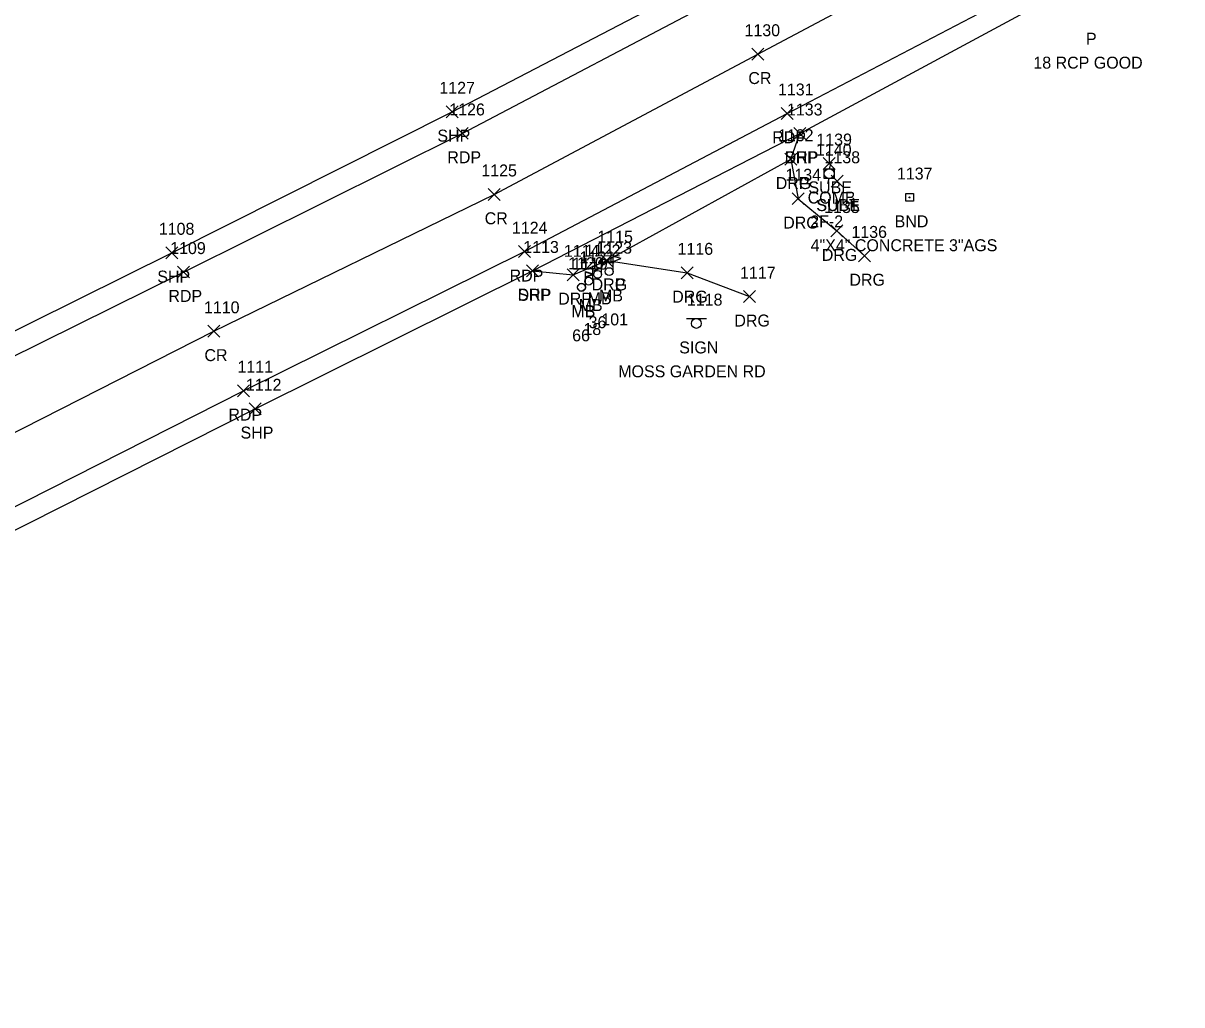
# Model space of a CAD drawing. Extents: x 1606530 to 1613020, y 784959 to 789666.
# Drawn here: x 1608391.2 to 1608585, y 787945.8 to 788110.1 of the extents above; entities that cross this region are included whole.
import ezdxf

# ---------------------------------------------------------------- set-up
doc = ezdxf.new("R2010")
doc.units = 0
for name, color, linetype in [('D_A', 7, 'Continuous'), ('D_C', 7, 'Continuous'), ('L_A', 7, 'Continuous'), ('L_C', 7, 'Continuous'), ('L_I', 7, 'Continuous'), ('LMB', 7, 'Continuous'), ('M_A', 7, 'Continuous'), ('M_C', 7, 'Continuous'), ('M_I', 7, 'Continuous'), ('MHBP', 7, 'Continuous'), ('P_A', 7, 'Continuous'), ('P_I', 7, 'Continuous'), ('P_TIC', 7, 'Continuous'), ('PET', 7, 'Continuous'), ('PRC', 7, 'Continuous'), ('PSP', 7, 'Continuous'), ('R_A', 7, 'Continuous'), ('R_I', 7, 'Continuous'), ('R_TIC', 7, 'Continuous'), ('RDG', 7, 'Continuous'), ('RDP', 7, 'Continuous'), ('S_A', 7, 'Continuous'), ('S_C', 7, 'Continuous'), ('S_I', 7, 'Continuous'), ('SSGN', 7, 'Continuous'), ('U_A', 7, 'Continuous'), ('U_C', 7, 'Continuous'), ('U_I', 7, 'Continuous'), ('U_TIC', 7, 'Continuous'), ('UP', 7, 'Continuous')]:
    doc.layers.add(name, color=color, linetype=linetype)

msp = doc.modelspace()

# ---------------------------------------------------------------- linework, layer by layer
at = {"layer": 'LMB'}
for p, q in [((1608487.94, 788070.66), (1608489.23, 788070.28)), ((1608487.94, 788068.07), (1608487.94, 788070.66)), ((1608487.94, 788069.76), (1608489.22, 788070.27)), ((1608489.86, 788071.13), (1608491.15, 788070.75)), ((1608489.86, 788068.54), (1608489.86, 788071.13)), ((1608489.86, 788070.23), (1608491.14, 788070.74)), ((1608485.23, 788065.94), (1608485.22, 788068.54)), ((1608485.22, 788068.53), (1608486.51, 788068.15)), ((1608485.22, 788067.63), (1608486.51, 788068.14)), ((1608485.23, 788068.46), (1608486.53, 788068.08)), ((1608485.24, 788065.87), (1608485.24, 788068.46)), ((1608485.24, 788067.56), (1608486.52, 788068.07)), ((1608486.45, 788069.52), (1608487.74, 788069.13)), ((1608486.45, 788066.92), (1608486.45, 788069.52)), ((1608486.45, 788068.62), (1608487.73, 788069.13)), ((1608487.29, 788068.06), (1608487.29, 788068.06)), ((1608489.21, 788068.53), (1608489.21, 788068.53)), ((1608484.57, 788065.93), (1608484.57, 788065.93)), ((1608485.8, 788066.92), (1608485.8, 788066.92)), ((1608484.58, 788065.86), (1608484.58, 788065.86))]:
    msp.add_line(p, q, dxfattribs=at)
for centre in [(1608487.29, 788068.06), (1608489.21, 788068.53), (1608484.57, 788065.93), (1608484.58, 788065.86), (1608485.8, 788066.92)]:
    msp.add_circle(centre, 0.656, dxfattribs=at)
at = {"layer": 'MHBP'}
msp.add_lwpolyline([(1608538.85, 788081.57), (1608540.1, 788081.57), (1608540.1, 788080.32), (1608538.85, 788080.32)], close=True, dxfattribs=at)
msp.add_circle((1608539.47, 788080.94), 0.0833, dxfattribs=at)
at = {"layer": 'P_TIC'}
for points in [[(1608513.06, 788103.91), (1608515.06, 788105.91)], [(1608515.06, 788103.91), (1608513.06, 788105.91)], [(1608461.93, 788094.28), (1608463.93, 788096.28)], [(1608463.93, 788094.28), (1608461.93, 788096.28)], [(1608518, 788094), (1608520, 788096)], [(1608520, 788094), (1608518, 788096)], [(1608463.64, 788090.66), (1608465.64, 788092.66)], [(1608465.64, 788090.66), (1608463.64, 788092.66)], [(1608520.08, 788090.65), (1608522.08, 788092.65)], [(1608522.08, 788090.65), (1608520.08, 788092.65)], [(1608468.95, 788080.45), (1608470.95, 788082.45)], [(1608470.95, 788080.45), (1608468.95, 788082.45)], [(1608415.07, 788070.69), (1608417.07, 788072.69)], [(1608417.07, 788070.69), (1608415.07, 788072.69)], [(1608474.06, 788070.87), (1608476.06, 788072.87)], [(1608476.06, 788070.87), (1608474.06, 788072.87)], [(1608416.98, 788067.46), (1608418.98, 788069.46)], [(1608418.98, 788067.46), (1608416.98, 788069.46)], [(1608475.4, 788067.65), (1608477.4, 788069.65)], [(1608477.4, 788067.65), (1608475.4, 788069.65)], [(1608422.06, 788057.55), (1608424.06, 788059.55)], [(1608424.06, 788057.55), (1608422.06, 788059.55)], [(1608427.02, 788047.6), (1608429.02, 788049.6)], [(1608429.02, 788047.6), (1608427.02, 788049.6)], [(1608429, 788044.59), (1608431, 788046.59)], [(1608431, 788044.59), (1608429, 788046.59)]]:
    msp.add_lwpolyline(points, dxfattribs=at)
at = {"layer": 'PET'}
for points in [[(1608213.49, 787970.47), (1608262.25, 787993.4), (1608276.88, 787999.74), (1608323.57, 788022.14), (1608370.66, 788045.01), (1608417.98, 788068.46), (1608464.64, 788091.66), (1608509.37, 788115.25), (1608554.28, 788138.75), (1608602.43, 788165), (1608652.45, 788192.19), (1608697.7, 788217.31), (1608740.32, 788241.6), (1608780.44, 788265.54), (1608814.8, 788285.27), (1608858.1, 788310.73), (1608896.56, 788332.46)], [(1608222.94, 787950.09), (1608271.33, 787972.62), (1608285.55, 787979.14), (1608332.21, 788001.49), (1608379.48, 788024.01), (1608428.02, 788048.6), (1608475.06, 788071.87), (1608519, 788095), (1608563.86, 788118.44), (1608613.21, 788145.21), (1608663.01, 788172.64), (1608706.97, 788197.28), (1608750.94, 788222.17), (1608791.64, 788245.74), (1608827.2, 788266.24), (1608867.86, 788290.54)]]:
    msp.add_lwpolyline(points, dxfattribs=at)
at = {"layer": 'PRC'}
msp.add_lwpolyline([(1608218.84, 787960.71), (1608267.22, 787983.04), (1608281.29, 787989.52), (1608328.06, 788011.76), (1608375.14, 788034.19), (1608423.06, 788058.55), (1608469.95, 788081.45), (1608514.06, 788104.91), (1608558.92, 788128.79), (1608607.88, 788155.22), (1608657.8, 788182.27), (1608701.47, 788207.47), (1608744.76, 788231.88), (1608785.13, 788255.45), (1608820.6, 788275.76), (1608863.25, 788300.9), (1608901.81, 788322.6)], dxfattribs=at)
at = {"layer": 'PSP'}
for points in [[(1608211.38, 787974.27), (1608260.55, 787996.78), (1608275.47, 788003.59), (1608321.31, 788025.42), (1608369.02, 788048.35), (1608416.07, 788071.69), (1608462.93, 788095.28), (1608507.55, 788118.54), (1608552.21, 788141.92), (1608600.4, 788168.18), (1608650.82, 788195.72), (1608695.96, 788221.19), (1608744.94, 788249.39), (1608760.2, 788258.36), (1608792.98, 788277.31), (1608812.41, 788289.29), (1608855.39, 788314.11), (1608894.81, 788336.59)], [(1608222.38, 787945.84), (1608249.08, 787958.77), (1608292.52, 787977.73), (1608320.86, 787991.5), (1608334.01, 787997.98), (1608381.01, 788020.88), (1608430, 788045.59), (1608476.4, 788068.65), (1608521.08, 788091.65), (1608567.38, 788116.6), (1608615.07, 788142.28), (1608664.87, 788169.33), (1608708.99, 788194), (1608752.22, 788219.24), (1608792.93, 788243.28), (1608830.36, 788265), (1608869.22, 788287.4)]]:
    msp.add_lwpolyline(points, dxfattribs=at)
at = {"layer": 'R_TIC'}
for points in [[(1608520.08, 788090.65), (1608522.08, 788092.65)], [(1608522.08, 788090.65), (1608520.08, 788092.65)], [(1608518.58, 788086.34), (1608520.58, 788088.34)], [(1608520.58, 788086.34), (1608518.58, 788088.34)], [(1608518.58, 788086.34), (1608520.58, 788088.34)], [(1608520.58, 788086.34), (1608518.58, 788088.34)], [(1608519.83, 788079.73), (1608521.83, 788081.73)], [(1608521.83, 788079.73), (1608519.83, 788081.73)], [(1608526.3, 788074.33), (1608528.3, 788076.33)], [(1608528.3, 788074.33), (1608526.3, 788076.33)], [(1608530.91, 788070.17), (1608532.91, 788072.17)], [(1608532.91, 788070.17), (1608530.91, 788072.17)], [(1608487.79, 788069.38), (1608489.79, 788071.38)], [(1608489.79, 788069.38), (1608487.79, 788071.38)], [(1608487.79, 788069.38), (1608489.79, 788071.38)], [(1608489.79, 788069.38), (1608487.79, 788071.38)], [(1608475.4, 788067.65), (1608477.4, 788069.65)], [(1608477.4, 788067.65), (1608475.4, 788069.65)], [(1608482.19, 788067), (1608484.19, 788069)], [(1608484.19, 788067), (1608482.19, 788069)], [(1608501.26, 788067.34), (1608503.26, 788069.34)], [(1608503.26, 788067.34), (1608501.26, 788069.34)], [(1608511.66, 788063.34), (1608513.66, 788065.34)], [(1608513.66, 788063.34), (1608511.66, 788065.34)]]:
    msp.add_lwpolyline(points, dxfattribs=at)
at = {"layer": 'RDG'}
for points in [[(1608519.58, 788087.34), (1608520.83, 788080.73), (1608527.3, 788075.33), (1608531.91, 788071.17)], [(1608488.79, 788070.38), (1608502.26, 788068.34), (1608512.66, 788064.34)]]:
    msp.add_lwpolyline(points, dxfattribs=at)
at = {"layer": 'RDP'}
msp.add_lwpolyline([(1608476.4, 788068.65), (1608483.19, 788068), (1608488.79, 788070.38), (1608519.58, 788087.34), (1608521.08, 788091.65)], dxfattribs=at)
at = {"layer": 'SSGN'}
for p, q in [((1608502.14, 788060.7), (1608505.47, 788060.7)), ((1608503.79, 788059.86), (1608503.79, 788059.86))]:
    msp.add_line(p, q, dxfattribs=at)
msp.add_circle((1608503.79, 788059.86), 0.833, dxfattribs=at)
at = {"layer": 'U_TIC'}
for points in [[(1608525, 788085.62), (1608527, 788087.62)], [(1608527, 788085.62), (1608525, 788087.62)], [(1608526.36, 788082.66), (1608528.36, 788084.66)], [(1608528.36, 788082.66), (1608526.36, 788084.66)], [(1608526.36, 788082.66), (1608528.36, 788084.66)], [(1608528.36, 788082.66), (1608526.36, 788084.66)]]:
    msp.add_lwpolyline(points, dxfattribs=at)
at = {"layer": 'UP'}
for p, q in [((1608525.19, 788084.09), (1608525.19, 788085.75)), ((1608525.19, 788085.75), (1608526.85, 788085.75)), ((1608526.27, 788086.59), (1608526.02, 788085.75)), ((1608526.85, 788085.75), (1608526.85, 788084.09)), ((1608526.85, 788084.09), (1608525.19, 788084.09)), ((1608525.77, 788083.25), (1608526.02, 788084.09)), ((1608526.02, 788084.92), (1608526.02, 788084.92))]:
    msp.add_line(p, q, dxfattribs=at)
msp.add_circle((1608526.02, 788084.92), 0.833, dxfattribs=at)

# ---------------------------------------------------------------- texts
at = {"layer": 'D_A'}
msp.add_text('P', height=2, dxfattribs=at).set_placement((1608568.97, 788106.49))
at = {"layer": 'D_C'}
msp.add_text('18 RCP GOOD', height=2, dxfattribs=at).set_placement((1608560.17, 788102.49))
at = {"layer": 'L_A'}
for p in [(1608485.59, 788063.06), (1608487.51, 788063.53), (1608482.88, 788060.93), (1608482.89, 788060.86), (1608484.1, 788061.92)]:
    msp.add_text('MB', height=2, dxfattribs=at).set_placement(p)
at = {"layer": 'L_C'}
for s, p in [('36', (1608485.77, 788059.06)), ('101', (1608487.9, 788059.53)), ('66', (1608483.02, 788056.86)), ('18', (1608484.9, 788057.92))]:
    msp.add_text(s, height=2, dxfattribs=at).set_placement(p)
at = {"layer": 'L_I'}
for s, p in [('1121', (1608484.24, 788069.92)), ('1122', (1608485.16, 788071.06)), ('1123', (1608487.08, 788071.53)), ('1120', (1608482.36, 788068.93)), ('1119', (1608483.02, 788068.86))]:
    msp.add_text(s, height=2, dxfattribs=at).set_placement(p)
at = {"layer": 'M_A'}
msp.add_text('BND', height=2, dxfattribs=at).set_placement((1608536.96, 788075.94))
at = {"layer": 'M_C'}
msp.add_text('4"X4" CONCRETE 3"AGS', height=2, dxfattribs=at).set_placement((1608522.91, 788071.94))
at = {"layer": 'M_I'}
msp.add_text('1137', height=2, dxfattribs=at).set_placement((1608537.35, 788083.94))
at = {"layer": 'P_A'}
for s, p in [('CR', (1608512.49, 788099.91)), ('SHP', (1608460.47, 788090.28)), ('RDP', (1608516.49, 788090)), ('RDP', (1608462.13, 788086.66)), ('SHP', (1608518.61, 788086.65)), ('CR', (1608468.38, 788076.45)), ('SHP', (1608413.61, 788066.69)), ('RDP', (1608472.55, 788066.87)), ('RDP', (1608415.47, 788063.46)), ('SHP', (1608473.94, 788063.65)), ('CR', (1608421.5, 788053.55)), ('RDP', (1608425.51, 788043.6)), ('SHP', (1608427.54, 788040.59))]:
    msp.add_text(s, height=2, dxfattribs=at).set_placement(p)
at = {"layer": 'P_I'}
for s, p in [('1130', (1608511.85, 788107.91)), ('1127', (1608460.8, 788098.28)), ('1131', (1608517.45, 788098)), ('1126', (1608462.46, 788094.66)), ('1133', (1608518.95, 788094.65)), ('1125', (1608467.82, 788084.45)), ('1108', (1608413.87, 788074.69)), ('1124', (1608472.94, 788074.87)), ('1113', (1608474.84, 788071.65)), ('1109', (1608415.77, 788071.46)), ('1110', (1608421.42, 788061.55)), ('1111', (1608427.03, 788051.6)), ('1112', (1608428.44, 788048.59))]:
    msp.add_text(s, height=2, dxfattribs=at).set_placement(p)
at = {"layer": 'R_A'}
for s, p in [('DRP', (1608518.56, 788086.65)), ('DRG', (1608517.07, 788082.34)), ('DRP', (1608517.07, 788082.34)), ('DRG', (1608518.32, 788075.73)), ('DRG', (1608524.78, 788070.33)), ('DRG', (1608529.4, 788066.17)), ('DRG', (1608486.27, 788065.38)), ('DRP', (1608486.27, 788065.38)), ('DRP', (1608473.89, 788063.65)), ('DRP', (1608480.68, 788063)), ('DRG', (1608499.75, 788063.34)), ('DRG', (1608510.15, 788059.34))]:
    msp.add_text(s, height=2, dxfattribs=at).set_placement(p)
at = {"layer": 'R_I'}
for s, p in [('1133', (1608518.95, 788094.65)), ('1132', (1608517.45, 788090.34)), ('1132', (1608517.45, 788090.34)), ('1134', (1608518.7, 788083.73)), ('1135', (1608525.17, 788078.33)), ('1136', (1608529.73, 788074.17)), ('1113', (1608474.84, 788071.65)), ('1115', (1608487.23, 788073.38)), ('1115', (1608487.23, 788073.38)), ('1114', (1608481.63, 788071)), ('1116', (1608500.65, 788071.34)), ('1117', (1608511.1, 788067.34))]:
    msp.add_text(s, height=2, dxfattribs=at).set_placement(p)
at = {"layer": 'S_A'}
msp.add_text('SIGN', height=2, dxfattribs=at).set_placement((1608500.93, 788054.84))
at = {"layer": 'S_C'}
msp.add_text('MOSS GARDEN RD', height=2, dxfattribs=at).set_placement((1608490.72, 788050.84))
at = {"layer": 'S_I'}
msp.add_text('1118', height=2, dxfattribs=at).set_placement((1608502.21, 788062.84))
at = {"layer": 'U_A'}
for s, p in [('SUBE', (1608522.54, 788081.62)), ('COMB', (1608522.41, 788079.92)), ('SUBT', (1608523.85, 788078.66)), ('SUBE', (1608523.89, 788078.66))]:
    msp.add_text(s, height=2, dxfattribs=at).set_placement(p)
at = {"layer": 'U_C'}
msp.add_text('2F-2', height=2, dxfattribs=at).set_placement((1608522.84, 788075.92))
at = {"layer": 'U_I'}
for s, p in [('1139', (1608523.87, 788089.62)), ('1140', (1608523.81, 788087.92)), ('1138', (1608525.23, 788086.66)), ('1138', (1608525.23, 788086.66))]:
    msp.add_text(s, height=2, dxfattribs=at).set_placement(p)

doc.saveas('drawing.dxf')
